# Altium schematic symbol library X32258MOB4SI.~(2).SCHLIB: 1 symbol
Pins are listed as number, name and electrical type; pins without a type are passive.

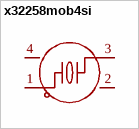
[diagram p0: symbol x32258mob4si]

## x32258mob4si
designator X??  (value not drawn)
晶振类型:贴片晶振;频率:8MHz;常温频差:±10ppm;负载电容:12pF;频率稳定度:±20ppm;; Manufacturer: YXC(扬兴晶振); AddInBom: yes; ModelId: ff2dfd5650294453a14147960efe1838; ModelName: CRYSTAL-SMD_4P-L3.2-W2.5-BL; ModelTransform: 125.984,98.425,0,0,0,0,0,0,0; Value: 8MHz; Normal temperature Frequency Tolerance: ±10ppm; Load Capacitance: 12pF; Frequency Stability: ±20ppm; Equivalent Series Resistance(ESR): 180Ω
footprint CRYSTAL-SMD_4P-L3.2-W2.5-BL (Footprint not found)
pins: 1, 2 GND, 3, 4 GND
